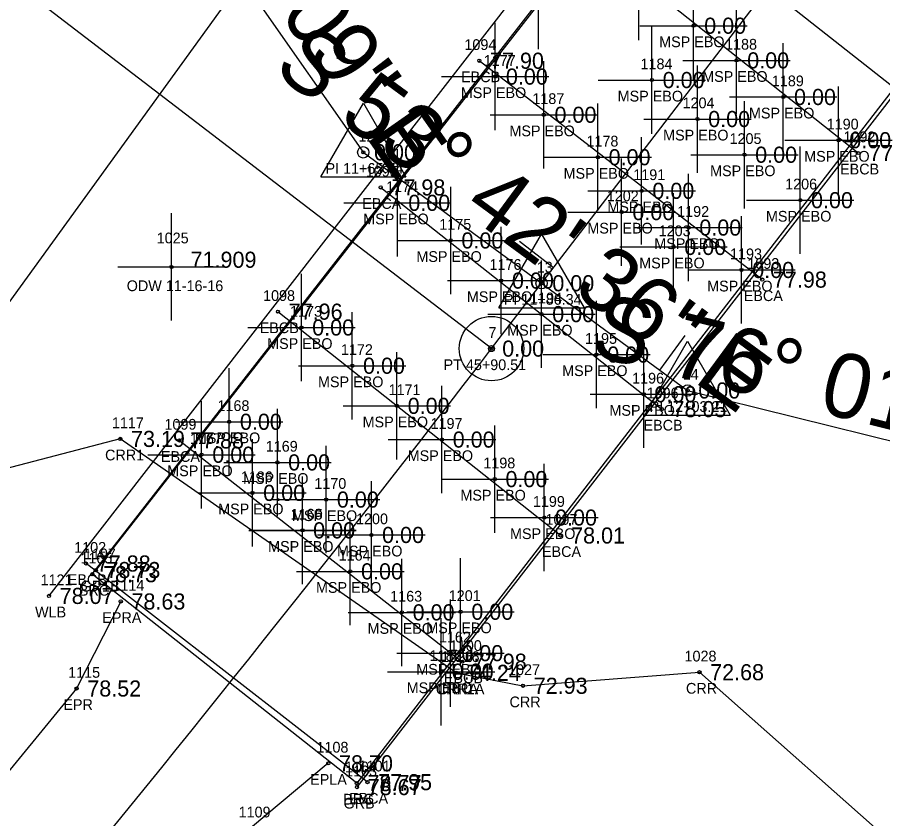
# Model space of a CAD drawing. Extents: x 2505249 to 2506333, y 912937 to 914171.
# Drawn here: x 2505748.6 to 2505829.2, y 913450.7 to 913525.4 of the extents above; entities that cross this region are included whole.
import ezdxf

# ---------------------------------------------------------------- set-up
doc = ezdxf.new("R2010")
doc.units = 0
for name, color, linetype in [('RD_EX_Bridge', 7, 'Continuous'), ('RD_EX_Bridge_txCode', 7, 'Continuous'), ('RD_EX_GuardRail', 7, 'Continuous'), ('RD_EX_GuardRail_txCode', 7, 'Continuous'), ('RD_EX_H2O', 7, 'Continuous'), ('RD_EX_H2O_txCode', 7, 'Continuous'), ('RD_EX_Misc', 7, 'Continuous'), ('RD_EX_Misc_txCode', 7, 'Continuous'), ('RD_EX_Road', 7, 'Continuous'), ('RD_EX_Road_txCode', 7, 'Continuous'), ('RD_EX_TX_Bridge_ELEV', 7, 'Continuous'), ('RD_EX_TX_GuardRail_ELEV', 7, 'Continuous'), ('RD_EX_TX_H2O_ELEV', 7, 'Continuous'), ('RD_EX_TX_Misc_ELEV', 7, 'Continuous'), ('RD_EX_TX_Road_ELEV', 7, 'Continuous'), ('RD_EX_TX_UT_ELEV', 7, 'Continuous'), ('RD_EX_UT', 7, 'Continuous'), ('RD_EX_UT_txCode', 7, 'Continuous'), ('RD_EX_VEG', 7, 'Continuous'), ('RD_HC_Cl', 7, 'Continuous'), ('RD_HC_Data', 7, 'Continuous'), ('RD_HC_Data_Tic', 7, 'Continuous'), ('RD_HC_Survey_ELEV', 7, 'Continuous'), ('RD_HC_txCode', 7, 'Continuous'), ('RD_SMD_Locator', 7, 'Continuous')]:
    doc.layers.add(name, color=color, linetype=linetype)

msp = doc.modelspace()

# ---------------------------------------------------------------- linework, layer by layer
at = {"layer": 'RD_EX_Bridge'}
for p, q in [((2505800.831, 913533.486), (2505826.933, 913512.731)), ((2505817.979, 913500.935), (2505791.626, 913521.322)), ((2505782.441, 913509.521), (2505808.625, 913488.875)), ((2505799.18, 913477.102), (2505772.871, 913497.948)), ((2505763.685, 913485.957), (2505790.024, 913465.345)), ((2505781.205, 913454.129), (2505754.992, 913474.491))]:
    msp.add_line(p, q, dxfattribs=at)
msp.add_lwpolyline([(2505810.902, 913544.512), (2505835.376, 913525.368), (2505780.208, 913454.04), (2505755.58, 913473.496), (2505810.902, 913544.512)], dxfattribs=at)
at = {"layer": 'RD_EX_GuardRail'}
for p, q in [((2505810.689, 913543.934), (2505755.898, 913473.882)), ((2505835.697, 913525.243), (2505780.232, 913453.668))]:
    msp.add_line(p, q, dxfattribs=at)
at = {"layer": 'RD_EX_H2O'}
for points in [[(2505762.262, 913658.109), (2505746.145, 913644.246), (2505726.467, 913615.205), (2505674.206, 913628.007), (2505666.247, 913620.583), (2505714.598, 913592.147), (2505793.902, 913560.447), (2505801.323, 913552.799), (2505803.704, 913539.769), (2505832.625, 913516.964), (2505848.424, 913517.193), (2505881.862, 913528.443), (2505910.198, 913538.779), (2505939.304, 913544.448), (2505946.254, 913542.537), (2505974.653, 913535.178), (2506004.111, 913524.704), (2506052.031, 913515.471), (2506115.491, 913494.68), (2506138.045, 913548.886)], [(2505789.475, 913464.314), (2505758.184, 913486.097), (2505736.661, 913480.486), (2505719.324, 913463.858), (2505699.898, 913439.205), (2505669.03, 913402.749), (2505628.504, 913357.896), (2505592.999, 913316.388), (2505556.585, 913279.798), (2505487.724, 913211.376), (2505413.809, 913149.811), (2505341.309, 913072.101)], [(2505789.475, 913464.314), (2505795.694, 913463.103), (2505812.13, 913464.368), (2505832.031, 913446.726), (2505876.169, 913453.079), (2505891.756, 913474.027), (2505941.737, 913475.129), (2505995.42, 913465.054), (2506040.13, 913447.397), (2506076.302, 913432.472), (2506096.958, 913385.48)]]:
    msp.add_lwpolyline(points, dxfattribs=at)
at = {"layer": 'RD_EX_Misc'}
for p, q in [((2505806.486, 913523.247), (2505806.486, 913533.247)), ((2505797.132, 913522.39), (2505797.132, 913532.39)), ((2505811.577, 913519.584), (2505811.577, 913529.584)), ((2505815.584, 913516.355), (2505815.584, 913526.355)), ((2505793.104, 913514.844), (2505793.104, 913524.844)), ((2505806.577, 913524.584), (2505816.577, 913524.584)), ((2505807.709, 913514.525), (2505807.709, 913524.525)), ((2505819.943, 913512.944), (2505819.943, 913522.944)), ((2505797.631, 913511.289), (2505797.631, 913521.289)), ((2505810.584, 913521.355), (2505820.584, 913521.355)), ((2505811.946, 913510.893), (2505811.946, 913520.893)), ((2505788.104, 913519.844), (2505798.104, 913519.844)), ((2505802.709, 913519.525), (2505812.709, 913519.525)), ((2505825.089, 913508.918), (2505825.089, 913518.918)), ((2505814.943, 913517.944), (2505824.943, 913517.944)), ((2505802.672, 913507.332), (2505802.672, 913517.332)), ((2505816.324, 913507.568), (2505816.324, 913517.568)), ((2505792.631, 913516.289), (2505802.631, 913516.289)), ((2505806.946, 913515.893), (2505816.946, 913515.893)), ((2505806.75, 913504.206), (2505806.75, 913514.206)), ((2505820.089, 913513.918), (2505830.089, 913513.918)), ((2505784.012, 913503.085), (2505784.012, 913513.085)), ((2505821.526, 913503.334), (2505821.526, 913513.334)), ((2505797.672, 913512.332), (2505807.672, 913512.332)), ((2505804.887, 913502.227), (2505804.887, 913512.227)), ((2505811.324, 913512.568), (2505821.324, 913512.568)), ((2505811.122, 913500.782), (2505811.122, 913510.782)), ((2505788.962, 913499.584), (2505788.962, 913509.584)), ((2505801.75, 913509.206), (2505811.75, 913509.206)), ((2505809.72, 913498.979), (2505809.72, 913508.979)), ((2505816.526, 913508.334), (2505826.526, 913508.334)), ((2505779.012, 913508.085), (2505789.012, 913508.085)), ((2505762.963, 913497.111), (2505762.963, 913507.111)), ((2505799.887, 913507.227), (2505809.887, 913507.227)), ((2505816.048, 913496.833), (2505816.048, 913506.833)), ((2505793.665, 913495.843), (2505793.665, 913505.843)), ((2505806.122, 913505.782), (2505816.122, 913505.782)), ((2505783.962, 913504.584), (2505793.962, 913504.584)), ((2505804.72, 913503.979), (2505814.72, 913503.979)), ((2505797.419, 913492.723), (2505797.419, 913502.723)), ((2505757.963, 913502.111), (2505767.963, 913502.111)), ((2505811.048, 913501.833), (2505821.048, 913501.833)), ((2505775.061, 913491.477), (2505775.061, 913501.477)), ((2505788.665, 913500.843), (2505798.665, 913500.843)), ((2505802.54, 913488.952), (2505802.54, 913498.952)), ((2505779.798, 913487.914), (2505779.798, 913497.914)), ((2505792.419, 913497.723), (2505802.419, 913497.723)), ((2505770.061, 913496.477), (2505780.061, 913496.477)), ((2505806.947, 913485.255), (2505806.947, 913495.255)), ((2505783.954, 913484.176), (2505783.954, 913494.176)), ((2505797.54, 913493.952), (2505807.54, 913493.952)), ((2505774.798, 913492.914), (2505784.798, 913492.914)), ((2505768.326, 913482.695), (2505768.326, 913492.695)), ((2505788.151, 913481.035), (2505788.151, 913491.035)), ((2505765.756, 913479.626), (2505765.756, 913489.626)), ((2505801.947, 913490.255), (2505811.947, 913490.255)), ((2505772.82, 913478.91), (2505772.82, 913488.91)), ((2505778.954, 913489.176), (2505788.954, 913489.176)), ((2505763.326, 913487.695), (2505773.326, 913487.695)), ((2505793.063, 913477.356), (2505793.063, 913487.356)), ((2505770.497, 913476.07), (2505770.497, 913486.07)), ((2505783.151, 913486.035), (2505793.151, 913486.035)), ((2505777.36, 913475.447), (2505777.36, 913485.447)), ((2505760.756, 913484.626), (2505770.756, 913484.626)), ((2505767.82, 913483.91), (2505777.82, 913483.91)), ((2505797.684, 913473.771), (2505797.684, 913483.771)), ((2505775.147, 913472.583), (2505775.147, 913482.583)), ((2505775.152, 913472.579), (2505775.152, 913482.579)), ((2505788.063, 913482.356), (2505798.063, 913482.356)), ((2505781.57, 913472.151), (2505781.57, 913482.151)), ((2505765.497, 913481.07), (2505775.497, 913481.07)), ((2505772.36, 913480.447), (2505782.36, 913480.447)), ((2505779.612, 913468.762), (2505779.612, 913478.762)), ((2505792.684, 913478.771), (2505802.684, 913478.771)), ((2505770.147, 913477.583), (2505780.147, 913477.583)), ((2505770.152, 913477.579), (2505780.152, 913477.579)), ((2505776.57, 913477.151), (2505786.57, 913477.151)), ((2505784.415, 913464.943), (2505784.415, 913474.943)), ((2505789.884, 913465), (2505789.884, 913475)), ((2505774.612, 913473.762), (2505784.612, 913473.762)), ((2505788.952, 913461.142), (2505788.952, 913471.142)), ((2505779.415, 913469.943), (2505789.415, 913469.943)), ((2505784.884, 913470), (2505794.884, 913470)), ((2505788.06, 913459.416), (2505788.06, 913469.416)), ((2505783.952, 913466.142), (2505793.952, 913466.142)), ((2505783.06, 913464.416), (2505793.06, 913464.416))]:
    msp.add_line(p, q, dxfattribs=at)
at = {"layer": 'RD_EX_Road'}
for points in [[(2505758.226, 913470.957), (2505754.109, 913462.851), (2505725.405, 913427.852), (2505690.772, 913387.11), (2505650.249, 913343.361), (2505607.723, 913300.123), (2505570.966, 913264.99), (2505501.533, 913196.719), (2505431.765, 913128.834), (2505356.25, 913055.365)], [(2505777.563, 913455.881), (2505770.308, 913449.845), (2505740.997, 913414.445), (2505705.546, 913374.273), (2505664.834, 913329.822), (2505624.02, 913288.229), (2505585.621, 913250.632), (2505516.952, 913183.495), (2505444.267, 913113.558), (2505370.603, 913041.775)]]:
    msp.add_lwpolyline(points, dxfattribs=at)
at = {"layer": 'RD_EX_UT'}
msp.add_line((2505812.637, 913550.177), (2505751.539, 913471.474), dxfattribs=at)
at = {"layer": 'RD_EX_VEG'}
msp.add_lwpolyline([(2506002.64, 913815.253), (2505883.703, 913669.642), (2505827.831, 913593.293), (2505814.43, 913589.154), (2505792.492, 913560.547), (2505725.635, 913468.235), (2505664.365, 913399.088), (2505478.329, 913221.003), (2505411.986, 913152.193), (2505339.126, 913074.528)], dxfattribs=at)
at = {"layer": 'RD_HC_Cl'}
for p, q in [((2505792.762, 913494.508), (2506032.344, 913807.095)), ((2505757.703, 913545.846), (2505780.822, 913512.79)), ((2505780.822, 913512.79), (2505811.027, 913490.61)), ((2505811.027, 913490.61), (2505846.35, 913481.822))]:
    msp.add_line(p, q, dxfattribs=at)
msp.add_arc((2504276.95, 914656.302), 1909.83, 314.242052, 322.531635, dxfattribs=at)
at = {"layer": 'RD_HC_Data'}
for p, q in [((2505792.762, 913494.508), (2505701.426, 913564.513)), ((2505776.852, 913510.497), (2505780.824, 913517.376)), ((2505780.824, 913517.376), (2505784.792, 913510.497)), ((2505776.852, 913510.497), (2505784.792, 913510.497)), ((2505793.457, 913498.303), (2505797.429, 913505.183)), ((2505797.429, 913505.183), (2505801.398, 913498.303)), ((2505793.457, 913498.303), (2505801.398, 913498.303)), ((2505807.056, 913488.318), (2505811.028, 913495.197)), ((2505811.028, 913495.197), (2505814.997, 913488.318)), ((2505807.056, 913488.318), (2505814.997, 913488.318))]:
    msp.add_line(p, q, dxfattribs=at)
for centre, radius in [((2505780.822, 913512.79), 0.529), ((2505797.428, 913500.596), 0.529), ((2505792.761, 913494.508), 3), ((2505792.761, 913494.508), 0.282), ((2505811.027, 913490.61), 0.529)]:
    msp.add_circle(centre, radius, dxfattribs=at)
at = {"layer": 'RD_HC_Data_Tic'}
for p, q in [((2505798.534, 913502.039), (2505795.359, 913504.472)), ((2505808.438, 913492.511), (2505810.806, 913495.735))]:
    msp.add_line(p, q, dxfattribs=at)
at = {"layer": 'RD_SMD_Locator'}
for centre in [(2505811.577, 913524.584), (2505791.626, 913521.322), (2505815.584, 913521.355), (2505793.104, 913519.844), (2505807.709, 913519.525), (2505819.943, 913517.944), (2505797.631, 913516.289), (2505811.946, 913515.893), (2505825.089, 913513.918), (2505780.822, 913512.79), (2505802.672, 913512.332), (2505816.324, 913512.568), (2505826.933, 913512.731), (2505782.441, 913509.521), (2505806.75, 913509.206), (2505784.012, 913508.085), (2505821.526, 913508.334), (2505804.887, 913507.227), (2505811.122, 913505.782), (2505788.962, 913504.584), (2505809.72, 913503.979), (2505762.963, 913502.111), (2505816.048, 913501.833), (2505793.665, 913500.843), (2505817.979, 913500.935), (2505797.428, 913500.596), (2505772.871, 913497.948), (2505797.419, 913497.723), (2505775.061, 913496.477), (2505792.761, 913494.508), (2505802.54, 913493.952), (2505779.798, 913492.914), (2505806.947, 913490.255), (2505811.027, 913490.61), (2505783.954, 913489.176), (2505808.625, 913488.875), (2505768.326, 913487.695), (2505758.184, 913486.097), (2505763.685, 913485.957), (2505788.151, 913486.035), (2505765.756, 913484.626), (2505772.82, 913483.91), (2505793.063, 913482.356), (2505770.497, 913481.07), (2505777.36, 913480.447), (2505797.684, 913478.771), (2505775.147, 913477.583), (2505775.152, 913477.579), (2505781.57, 913477.151), (2505799.18, 913477.102), (2505754.992, 913474.491), (2505755.58, 913473.496), (2505755.898, 913473.882), (2505779.612, 913473.762), (2505751.539, 913471.474), (2505758.226, 913470.957), (2505784.415, 913469.943), (2505789.884, 913470), (2505788.952, 913466.142), (2505790.024, 913465.345), (2505788.06, 913464.416), (2505789.475, 913464.314), (2505789.475, 913464.314), (2505812.13, 913464.368), (2505754.109, 913462.851), (2505795.694, 913463.103), (2505777.563, 913455.881), (2505780.208, 913454.04), (2505781.205, 913454.129), (2505780.232, 913453.668)]:
    msp.add_circle(centre, 0.15, dxfattribs=at)

# ---------------------------------------------------------------- texts
at = {"layer": 'RD_EX_Bridge_txCode'}
for s, p in [('1094', (2505790.24, 913522.322)), ('EBCB', (2505789.925, 913519.322)), ('1092', (2505825.548, 913513.731)), ('1095', (2505781.055, 913510.521)), ('EBCB', (2505825.233, 913510.731)), ('EBCA', (2505780.724, 913507.521)), ('1093', (2505816.593, 913501.935)), ('1098', (2505771.485, 913498.948)), ('EBCA', (2505816.263, 913498.935)), ('EBCB', (2505771.17, 913495.948)), ('1096', (2505807.215, 913489.875)), ('1099', (2505762.299, 913486.957)), ('EBCB', (2505806.924, 913486.875)), ('EBCA', (2505761.968, 913483.957)), ('1097', (2505797.794, 913478.102)), ('1102', (2505753.89, 913475.491)), ('EBCA', (2505797.464, 913475.102)), ('1105', (2505754.477, 913474.496)), ('EBCB', (2505753.291, 913472.491)), ('BRC', (2505754.328, 913471.496)), ('1100', (2505788.882, 913466.345)), ('EBCB', (2505788.323, 913463.345)), ('1104', (2505779.106, 913455.04)), ('1101', (2505780.386, 913455.129)), ('BRC', (2505778.956, 913452.04)), ('EBCA', (2505779.488, 913452.129))]:
    msp.add_text(s, height=1, dxfattribs=at).set_placement(p)
at = {"layer": 'RD_EX_GuardRail_txCode'}
for s, p in [('1107', (2505754.796, 913474.882)), ('GR1B', (2505754.481, 913471.882)), ('1103', (2505779.13, 913454.668)), ('GRB', (2505778.98, 913451.668))]:
    msp.add_text(s, height=1, dxfattribs=at).set_placement(p)
at = {"layer": 'RD_EX_H2O_txCode'}
for s, p in [('1117', (2505757.404, 913487.097)), ('CRR1', (2505756.766, 913484.097)), ('1026', (2505788.065, 913465.314)), ('1116', (2505788.672, 913465.314)), ('1028', (2505810.744, 913465.368)), ('1027', (2505794.309, 913464.103)), ('CRR1A', (2505787.569, 913462.314)), ('CRRA', (2505787.735, 913462.314)), ('CRR', (2505810.878, 913462.368)), ('CRR', (2505794.442, 913461.103))]:
    msp.add_text(s, height=1, dxfattribs=at).set_placement(p)
at = {"layer": 'RD_EX_Misc_txCode'}
for s, p in [('MSP EBO', (2505808.38, 913522.584)), ('1188', (2505814.521, 913522.355)), ('1177', (2505792.041, 913520.844)), ('1184', (2505806.646, 913520.525)), ('MSP EBO', (2505812.387, 913519.355)), ('1189', (2505818.88, 913518.944)), ('MSP EBO', (2505789.907, 913517.844)), ('1187', (2505796.568, 913517.289)), ('MSP EBO', (2505804.513, 913517.525)), ('1204', (2505810.56, 913516.893)), ('MSP EBO', (2505816.746, 913515.944)), ('1190', (2505823.987, 913514.918)), ('MSP EBO', (2505794.434, 913514.289)), ('MSP EBO', (2505808.749, 913513.893)), ('1205', (2505814.938, 913513.568)), ('1178', (2505801.609, 913513.332)), ('MSP EBO', (2505821.892, 913511.918)), ('MSP EBO', (2505813.127, 913510.568)), ('MSP EBO', (2505799.475, 913510.332)), ('1191', (2505805.97, 913510.206)), ('1174', (2505782.949, 913509.085)), ('1206', (2505820.116, 913509.334)), ('1202', (2505803.502, 913508.227)), ('MSP EBO', (2505803.553, 913507.206)), ('1192', (2505810.059, 913506.782)), ('MSP EBO', (2505818.329, 913506.334)), ('MSP EBO', (2505780.815, 913506.085)), ('1175', (2505787.899, 913505.584)), ('MSP EBO', (2505801.691, 913505.227)), ('1203', (2505808.334, 913504.979)), ('1025', (2505761.577, 913504.311)), ('MSP EBO', (2505807.925, 913503.782)), ('MSP EBO', (2505785.766, 913502.584)), ('1193', (2505814.985, 913502.833)), ('1176', (2505792.578, 913501.843)), ('MSP EBO', (2505806.523, 913501.979)), ('ODW 11-16-16 ', (2505758.785, 913499.86)), ('MSP EBO', (2505812.851, 913499.833)), ('MSP EBO', (2505790.468, 913498.843)), ('1194', (2505796.356, 913498.723)), ('1173', (2505773.998, 913497.477)), ('MSP EBO', (2505794.222, 913495.723)), ('MSP EBO', (2505771.864, 913494.477)), ('1195', (2505801.477, 913494.952)), ('1172', (2505778.735, 913493.914)), ('MSP EBO', (2505799.343, 913491.952)), ('1196', (2505805.86, 913491.255)), ('MSP EBO', (2505776.602, 913490.914)), ('1171', (2505783.175, 913490.176)), ('1168', (2505767.239, 913488.695)), ('MSP EBO', (2505803.75, 913488.255)), ('MSP EBO', (2505780.757, 913487.176)), ('1197', (2505787.088, 913487.035)), ('1167', (2505764.67, 913485.626)), ('MSP EBO', (2505765.129, 913485.695)), ('1169', (2505771.734, 913484.91)), ('MSP EBO', (2505784.954, 913484.035)), ('1198', (2505792, 913483.356)), ('MSP EBO', (2505762.559, 913482.626)), ('1186', (2505769.411, 913482.07)), ('MSP EBO', (2505769.624, 913481.91)), ('1170', (2505776.258, 913481.447)), ('MSP EBO', (2505789.866, 913480.356)), ('1199', (2505796.621, 913479.771)), ('MSP EBO', (2505767.3, 913479.07)), ('1166', (2505774.036, 913478.583)), ('1165', (2505774.065, 913478.579)), ('MSP EBO', (2505774.163, 913478.447)), ('1200', (2505780.144, 913478.151)), ('MSP EBO', (2505794.487, 913476.771)), ('MSP EBO', (2505771.95, 913475.583)), ('MSP EBO', (2505771.955, 913475.579)), ('MSP EBO', (2505778.373, 913475.151)), ('1164', (2505778.526, 913474.762)), ('MSP EBO', (2505776.415, 913471.762)), ('1163', (2505783.328, 913470.943)), ('1201', (2505788.782, 913471)), ('MSP EBO', (2505781.218, 913467.943)), ('MSP EBO', (2505786.687, 913468)), ('1162', (2505787.865, 913467.142)), ('1185', (2505786.997, 913465.416)), ('MSP EBO', (2505785.755, 913464.142)), ('MSP EBO', (2505784.863, 913462.416))]:
    msp.add_text(s, height=1, dxfattribs=at).set_placement(p)
at = {"layer": 'RD_EX_Road_txCode'}
for s, p in [('1114', (2505757.447, 913471.957)), ('EPRA', (2505756.51, 913468.957)), ('1115', (2505753.33, 913463.851)), ('EPR', (2505752.881, 913460.851)), ('1108', (2505776.461, 913456.881)), ('EPLA', (2505775.87, 913453.881)), ('1109', (2505769.206, 913450.845))]:
    msp.add_text(s, height=1, dxfattribs=at).set_placement(p)
at = {"layer": 'RD_EX_TX_Bridge_ELEV'}
for s, p in [('77.90', (2505792.626, 913520.572)), ('77.95', (2505827.933, 913511.981)), ('77.98', (2505783.441, 913508.771)), ('77.98', (2505818.979, 913500.185)), ('77.96', (2505773.871, 913497.198)), ('78.05', (2505809.625, 913488.125)), ('77.88', (2505764.685, 913485.207)), ('78.01', (2505800.18, 913476.352)), ('77.88', (2505755.992, 913473.741)), ('78.73', (2505756.58, 913472.746)), ('77.98', (2505791.024, 913464.595)), ('78.77', (2505781.208, 913453.29)), ('77.95', (2505782.205, 913453.379))]:
    msp.add_text(s, height=1.5, dxfattribs=at).set_placement(p)
at = {"layer": 'RD_EX_TX_GuardRail_ELEV'}
for s, p in [('78.73', (2505756.898, 913473.132)), ('78.67', (2505781.232, 913452.918))]:
    msp.add_text(s, height=1.5, dxfattribs=at).set_placement(p)
at = {"layer": 'RD_EX_TX_H2O_ELEV'}
for s, p in [('73.19', (2505759.184, 913485.347)), ('74.24', (2505790.475, 913463.564)), ('74.24', (2505790.475, 913463.564)), ('72.68', (2505813.13, 913463.618)), ('72.93', (2505796.694, 913462.353))]:
    msp.add_text(s, height=1.5, dxfattribs=at).set_placement(p)
at = {"layer": 'RD_EX_TX_Misc_ELEV'}
for s, p in [('0.00', (2505812.577, 913523.834)), ('0.00', (2505816.584, 913520.605)), ('0.00', (2505794.104, 913519.094)), ('0.00', (2505808.709, 913518.775)), ('0.00', (2505820.943, 913517.194)), ('0.00', (2505798.631, 913515.539)), ('0.00', (2505812.946, 913515.143)), ('0.00', (2505826.089, 913513.168)), ('0.00', (2505803.672, 913511.582)), ('0.00', (2505817.324, 913511.818)), ('0.00', (2505807.75, 913508.456)), ('0.00', (2505822.526, 913507.584)), ('0.00', (2505785.012, 913507.335)), ('0.00', (2505805.887, 913506.477)), ('0.00', (2505812.122, 913505.032)), ('0.00', (2505789.962, 913503.834)), ('0.00', (2505810.72, 913503.229)), ('71.909', (2505764.732, 913502.037)), ('0.00', (2505817.048, 913501.083)), ('0.00', (2505794.665, 913500.093)), ('0.00', (2505798.419, 913496.973)), ('0.00', (2505776.061, 913495.727)), ('0.00', (2505803.54, 913493.202)), ('0.00', (2505780.798, 913492.164)), ('0.00', (2505807.947, 913489.505)), ('0.00', (2505784.954, 913488.426)), ('0.00', (2505769.326, 913486.945)), ('0.00', (2505789.151, 913485.285)), ('0.00', (2505766.756, 913483.876)), ('0.00', (2505773.82, 913483.16)), ('0.00', (2505794.063, 913481.606)), ('0.00', (2505771.497, 913480.32)), ('0.00', (2505778.36, 913479.697)), ('0.00', (2505798.684, 913478.021)), ('0.00', (2505776.147, 913476.833)), ('0.00', (2505776.152, 913476.829)), ('0.00', (2505782.57, 913476.401)), ('0.00', (2505780.612, 913473.012)), ('0.00', (2505785.415, 913469.193)), ('0.00', (2505790.884, 913469.25)), ('0.00', (2505789.952, 913465.392)), ('0.00', (2505789.06, 913463.666))]:
    msp.add_text(s, height=1.5, dxfattribs=at).set_placement(p)
at = {"layer": 'RD_EX_TX_Road_ELEV'}
for s, p in [('78.63', (2505759.226, 913470.207)), ('78.52', (2505755.109, 913462.101)), ('78.70', (2505778.563, 913455.131))]:
    msp.add_text(s, height=1.5, dxfattribs=at).set_placement(p)
at = {"layer": 'RD_EX_TX_UT_ELEV'}
msp.add_text('78.07', height=1.5, dxfattribs=at).set_placement((2505752.539, 913470.724))
at = {"layer": 'RD_EX_UT_txCode'}
for s, p in [('1121', (2505750.759, 913472.474)), ('WLB', (2505750.247, 913469.474))]:
    msp.add_text(s, height=1, dxfattribs=at).set_placement(p)
at = {"layer": 'RD_HC_Data'}
for s, rotation, p in [('S 34%%d 58\' 09" E', 304.96917, (2505753.091, 913554.184)), ('S 53%%d 42\' 36" E', 323.70994, (2505772.278, 913520.304)), ('S 76%%d 01\' 43" E', 346.02866, (2505801.766, 913493.945))]:
    msp.add_text(s, height=6, rotation=rotation, dxfattribs=at).set_placement(p)
at = {"layer": 'RD_HC_Survey_ELEV'}
for p in [(2505781.822, 913512.04), (2505798.428, 913499.846), (2505793.761, 913493.758), (2505812.027, 913489.86)]:
    msp.add_text('0.00', height=1.5, dxfattribs=at).set_placement(p)
at = {"layer": 'RD_HC_txCode'}
for s, p in [('12', (2505780.373, 913513.79)), ('PI 11+65.74', (2505777.303, 913510.79)), ('13', (2505796.979, 913501.596)), ('PI 11+86.34', (2505793.908, 913498.596)), ('7', (2505792.478, 913495.508)), ('PT 45+90.51', (2505788.297, 913492.508)), ('14', (2505810.578, 913491.61)), ('PI 12+03.21', (2505807.491, 913488.61))]:
    msp.add_text(s, height=1, dxfattribs=at).set_placement(p)

doc.saveas('drawing.dxf')
